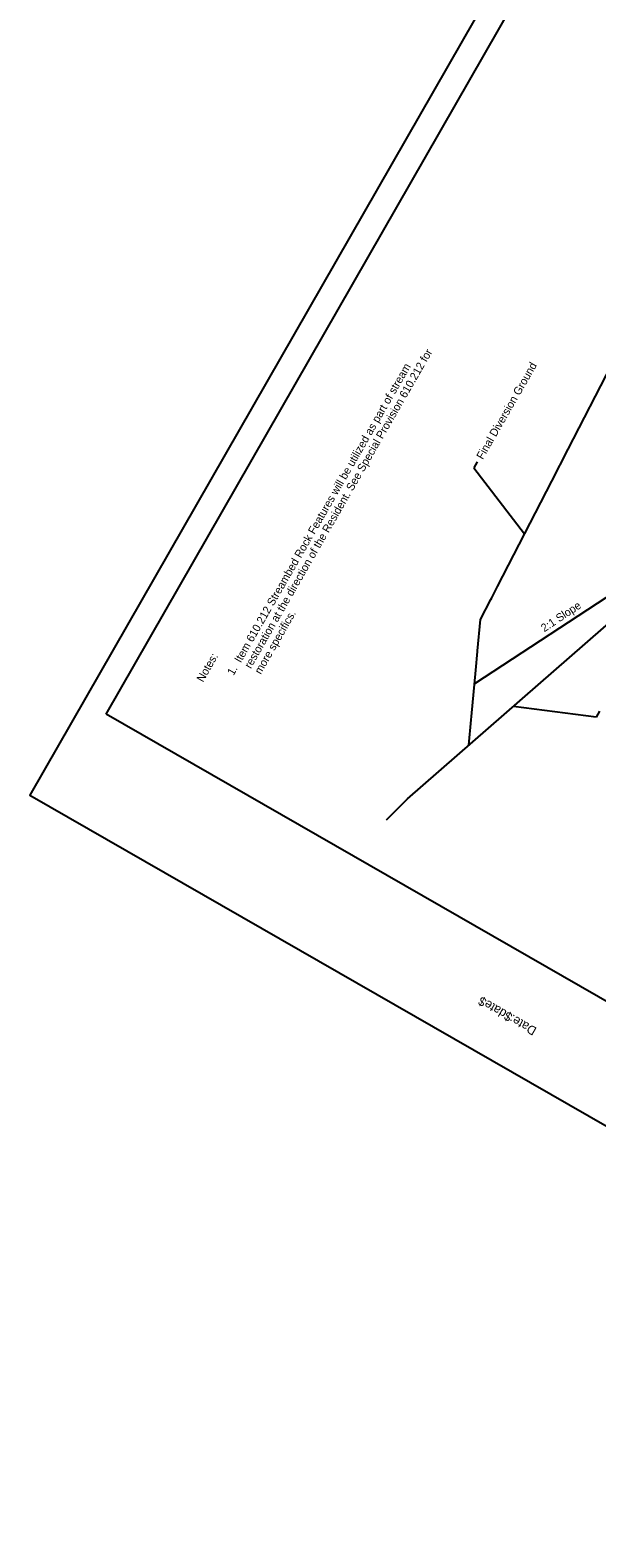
# Model space of a CAD drawing. Extents: x 1160918 to 1162032, y 616868 to 618272.
# Drawn here: x 1160918 to 1161130, y 616868 to 617428 of the extents above; entities that cross this region are included whole.
import ezdxf

# ---------------------------------------------------------------- set-up
doc = ezdxf.new("R2010")
doc.units = 0
for name, color, linetype in [('ANNOTATION', 7, 'Continuous'), ('BORDER', 7, 'Continuous'), ('D_Roadway_Centerline', 7, 'Continuous'), ('D_Roadway_Centerline_CurveData', 7, 'Continuous'), ('PLOT BOUNDARY', 7, 'Continuous'), ('S_Roadway_Centerline', 7, 'Continuous')]:
    doc.layers.add(name, color=color, linetype=linetype)

msp = doc.modelspace()

# ---------------------------------------------------------------- linework, layer by layer
at = {"layer": 'ANNOTATION'}
for p, q in [((1161085.24, 617266.53), (1161083.98, 617264.33)), ((1161083.98, 617264.33), (1161103.06, 617239.55)), ((1161129.89, 617170.86), (1161098.86, 617174.82)), ((1161131.15, 617173.06), (1161129.89, 617170.86))]:
    msp.add_line(p, q, dxfattribs=at)
at = {"layer": 'BORDER'}
msp.add_lwpolyline([(1160946.07, 617171.9), (1161344.12, 617865.84), (1161799.52, 617604.62), (1161401.47, 616910.68)], close=True, dxfattribs=at)
at = {"layer": 'D_Roadway_Centerline'}
msp.add_lwpolyline([(1161084.35, 617183.4), (1161151.39, 617227.32), (1161155.9, 617233.6), (1161172.14, 617262.58), (1161187.84, 617295.32), (1161192.39, 617300.62), (1161194.47, 617333.83), (1161195.48, 617349.39), (1161196.23, 617365.67), (1161196.56, 617365.98)], dxfattribs=at)
at = {"layer": 'PLOT BOUNDARY'}
msp.add_lwpolyline([(1161394.6, 616867.96), (1161817.53, 617605.28), (1161340.44, 617878.94), (1160917.52, 617141.62)], close=True, dxfattribs=at)
at = {"layer": 'S_Roadway_Centerline'}
for points in [[(1161051.23, 617132.33), (1161059.14, 617140.2), (1161138.59, 617209.45), (1161156.14, 617233.94), (1161171.73, 617261.73), (1161187.76, 617295.14), (1161194.77, 617303.43), (1161198.86, 617330.93), (1161209.57, 617376.77), (1161218.15, 617419.8), (1161219.3, 617424.37)], [(1161082.19, 617160.29), (1161083.08, 617169.78), (1161083.08, 617169.84), (1161083.2, 617171.1), (1161084.82, 617188.45), (1161085.44, 617195.46), (1161085.46, 617195.7), (1161086.5, 617207.39), (1161090.38, 617214.94), (1161090.72, 617215.59), (1161092.88, 617219.79), (1161113.23, 617259.32), (1161119.38, 617271.24), (1161135.76, 617303.05)]]:
    msp.add_lwpolyline(points, dxfattribs=at)

# ---------------------------------------------------------------- texts
at = {"layer": 'ANNOTATION'}
for s, p in [('restoration at the direction of the Resident. See Special Provision 610.212 for ', (1161000.36, 617188.8)), ('Item 610.212 Streambed Rock Features will be utilized as part of stream ', (1160996.61, 617190.96)), ('Final Diversion Ground', (1161087.39, 617267.17)), ('more specifics.', (1161004.12, 617186.65)), ('Notes:', (1160982.45, 617183.71)), ('1.', (1160993.89, 617186.23))]:
    msp.add_text(s, height=3, rotation=60.1613, dxfattribs=at).set_placement(p)
at = {"layer": 'BORDER'}
for s, p in [('$date$', (1161098.82, 617059.4)), ('Date:', (1161107.88, 617054.21))]:
    msp.add_text(s, height=3.348, rotation=150.1613, dxfattribs=at).set_placement(p)
at = {"layer": 'D_Roadway_Centerline_CurveData'}
msp.add_text('2:1 Slope', height=3, rotation=33.5408, dxfattribs=at).set_placement((1161110.44, 617202.61))

doc.saveas('drawing.dxf')
